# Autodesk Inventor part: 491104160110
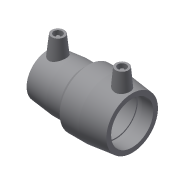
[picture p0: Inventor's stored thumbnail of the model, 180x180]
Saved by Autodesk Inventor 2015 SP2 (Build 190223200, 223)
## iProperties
Created: 2017-06
Part Number: 491104160110
Material: Generic
Description: PLASSON REDUCING COUPLER 160-110
Document SubType Name: Modeling
Designer: KIM
Mass: 54.8237 g
Surface Area: 155.252 cm^2
Volume: 54.8237 cm^3
Density: 1 g/cm^3
Appearance: Default
Author: KIM
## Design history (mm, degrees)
derived "491104.ipt"
feature "Solid1::491104.ipt"
tag "TaggingFeature1"
body "Solid1"
other parameters: "L_" = 193, "L_2" = 81, "D_1" = 141, "d_2" = 12, "L_1" = 94, "A_" = 105, "D_" = 199, "d0" = 193, "d2" = 141, "d3" = 81, "d4" = 48.6, "d5" = 126.9, "d8" = 168 deg, "d10" = 32.4, "d11" = 10.8, "d13" = 193, "d14" = 17.6296, "d15" = 81, "d19" = 4.05, "d20" = 168 deg, "d22" = 108.92847, "d25" = 135 deg, "d30" = 15, "d31" = 67.55, "d34" = 6 deg, "d35" = 15, "d38" = 19.5, "d39" = 5 deg, "d41" = 4, "d42" = 14, "d43" = 0, "d45" = 4, "d46" = 14, "d47" = 0, "d48" = 141, "d50" = 199, "d52" = 99, "d53" = 37.6, "d54" = 12.53333, "d55" = 168 deg, "d56" = 56.4, "d57" = 94, "d58" = 179.1, "d59" = 4.05, "d60" = 135 deg, "d61" = 105, "d62" = 15, "d64" = 4, "d66" = 5 deg, "d67" = 14, "d68" = 0, "d69" = 67.55, "d70" = 141, "d71" = 199, "d73" = 187.06, "d76" = 4.05, "d77" = 168 deg, "d79" = 4.05, "d80" = 94, "d81" = 99, "d82" = 132.54, "d83" = 120 deg, "d88" = 15, "d89" = 17, "d90" = 5 deg, "d92" = 4, "d93" = 14, "d94" = 0, "d95" = 3, "d96" = 0, "d97" = 3, "d98" = 0, "d99" = 23.49, "d100" = 5.8725, "d101" = 128.5638, "d102" = 20 deg, "d103" = 27.26, "d104" = 6.815, "d105" = 181.4482, "d106" = 3.60705, "d107" = 3, "d108" = 0, "d109" = 3, "d110" = 0
